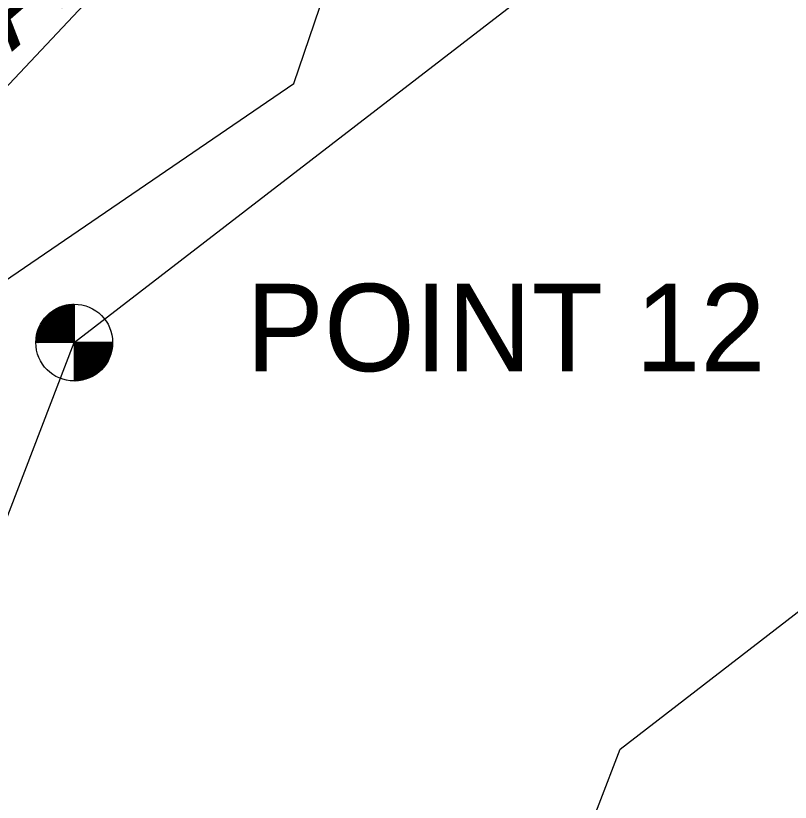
# Model space of a CAD drawing. Extents: x 2091245 to 2092168, y 863656 to 864307.
# Drawn here: x 2091740.16 to 2091775.62, y 863974.81 to 864010.83 of the extents above; entities that cross this region are included whole.
import ezdxf

# ---------------------------------------------------------------- set-up
doc = ezdxf.new("R2010")
doc.units = 0
for name, color, linetype in [('Exist Hydro Jurisdictional Stream or Body of Water', 7, 'Continuous'), ('Exist Hydrographic Top of Bank', 7, 'Continuous'), ('Prop Boundary Buffer Zone 1', 7, 'Continuous'), ('Prop Boundary Buffer Zone 2', 7, 'Continuous'), ('Scratch_Level_6', 7, 'Continuous')]:
    doc.layers.add(name, color=color, linetype=linetype)

msp = doc.modelspace()

# ---------------------------------------------------------------- linework, layer by layer
at = {"layer": 'Exist Hydro Jurisdictional Stream or Body of Water'}
msp.add_lwpolyline([(2091673.038, 863927.911), (2091672.627, 863930.924), (2091675.297, 863933.324), (2091682.95, 863933.761), (2091691.963, 863933.051), (2091695.28, 863934.846), (2091701.524, 863942.139), (2091700.79, 863950.834), (2091700.072, 863952.463), (2091701.052, 863960.667), (2091705.84, 863965.844), (2091716.038, 863968.921), (2091730.163, 863972.743), (2091727.795, 863981.975), (2091728.219, 863990.873), (2091752.896, 864007.718), (2091756.927, 864019.571), (2091767.092, 864026.792), (2091774.676, 864028.045), (2091779.207, 864034.48), (2091785.465, 864035.877), (2091790.325, 864037.563), (2091800.277, 864042.765), (2091802.985, 864045.288)], dxfattribs=at)
at = {"layer": 'Exist Hydrographic Top of Bank'}
msp.add_lwpolyline([(2091672.3, 863948.34), (2091672.795, 863927.55), (2091675.886, 863922.062), (2091703.915, 863935.563), (2091732.111, 863967.919), (2091742.84, 863995.86), (2091771.423, 864017.904), (2091796.939, 864035.122), (2091802.35, 864043.97), (2091798.347, 864050.35), (2091774.513, 864034.247), (2091751.1, 864019.64), (2091722.53, 863989.28), (2091717.91, 863987.56), (2091701.99, 863966.43)], close=True, dxfattribs=at)
at = {"layer": 'Prop Boundary Buffer Zone 1'}
msp.add_lwpolyline([(2091641.896, 863964.945), (2091642.981, 863919.351), (2091663.555, 863882.824), (2091722.485, 863911.209), (2091758.215, 863952.211), (2091767.828, 863977.246), (2091788.992, 863993.568), (2091819.128, 864013.904), (2091837.639, 864044.171), (2091807.267, 864092.583), (2091758.17, 864059.411), (2091731.919, 864043.033), (2091705.49, 864014.948), (2091699.226, 864012.616), (2091681.482, 863989.064)], close=True, dxfattribs=at)
at = {"layer": 'Prop Boundary Buffer Zone 2'}
msp.add_lwpolyline([(2091688.904, 863895.034), (2091722.485, 863911.209), (2091758.215, 863952.211), (2091767.828, 863977.246), (2091788.992, 863993.568), (2091813.72, 864010.255)], dxfattribs=at)
at = {"layer": 'Scratch_Level_6'}
for p, q in [((2091741.083, 863995.894), (2091742.806, 863997.617)), ((2091741.084, 863995.93), (2091742.77, 863997.616)), ((2091741.084, 863995.86), (2091742.84, 863997.616)), ((2091741.086, 863995.967), (2091742.733, 863997.614)), ((2091741.088, 863996.005), (2091742.694, 863997.611)), ((2091741.092, 863996.045), (2091742.656, 863997.608)), ((2091741.097, 863996.085), (2091742.615, 863997.603)), ((2091741.103, 863996.126), (2091742.574, 863997.597)), ((2091741.11, 863996.168), (2091742.532, 863997.59)), ((2091741.118, 863996.212), (2091742.488, 863997.582)), ((2091741.12, 863995.86), (2091742.84, 863997.58)), ((2091741.128, 863996.257), (2091742.443, 863997.572)), ((2091741.139, 863996.304), (2091742.396, 863997.56)), ((2091741.153, 863996.353), (2091742.347, 863997.547)), ((2091741.155, 863995.86), (2091742.84, 863997.545)), ((2091741.169, 863996.404), (2091742.296, 863997.531)), ((2091741.187, 863996.458), (2091742.242, 863997.513)), ((2091741.19, 863995.86), (2091742.84, 863997.51)), ((2091741.209, 863996.515), (2091742.185, 863997.491)), ((2091741.226, 863995.86), (2091742.84, 863997.474)), ((2091741.235, 863996.576), (2091742.123, 863997.465)), ((2091741.261, 863995.86), (2091742.84, 863997.439)), ((2091741.266, 863996.643), (2091742.057, 863997.433)), ((2091741.296, 863995.86), (2091742.84, 863997.404)), ((2091741.306, 863996.718), (2091741.982, 863997.394)), ((2091741.332, 863995.86), (2091742.84, 863997.368)), ((2091741.359, 863996.806), (2091741.894, 863997.341)), ((2091741.367, 863995.86), (2091742.84, 863997.333)), ((2091741.863, 863997.321), (2091742.84, 863996.344)), ((2091741.884, 863997.335), (2091742.84, 863996.379)), ((2091741.906, 863997.349), (2091742.84, 863996.415)), ((2091741.928, 863997.362), (2091742.84, 863996.45)), ((2091741.95, 863997.376), (2091742.84, 863996.485)), ((2091741.972, 863997.388), (2091742.84, 863996.521)), ((2091741.995, 863997.401), (2091742.84, 863996.556)), ((2091742.018, 863997.413), (2091742.84, 863996.592)), ((2091742.041, 863997.426), (2091742.84, 863996.627)), ((2091742.065, 863997.437), (2091742.84, 863996.662)), ((2091742.089, 863997.449), (2091742.84, 863996.698)), ((2091742.113, 863997.46), (2091742.84, 863996.733)), ((2091742.137, 863997.471), (2091742.84, 863996.768)), ((2091742.162, 863997.482), (2091742.84, 863996.804)), ((2091742.187, 863997.492), (2091742.84, 863996.839)), ((2091742.213, 863997.502), (2091742.84, 863996.874)), ((2091742.238, 863997.511), (2091742.84, 863996.91)), ((2091742.264, 863997.521), (2091742.84, 863996.945)), ((2091742.291, 863997.53), (2091742.84, 863996.98)), ((2091742.318, 863997.538), (2091742.84, 863997.016)), ((2091742.345, 863997.546), (2091742.84, 863997.051)), ((2091742.372, 863997.554), (2091742.84, 863997.087)), ((2091742.4, 863997.562), (2091742.84, 863997.122)), ((2091742.428, 863997.569), (2091742.84, 863997.157)), ((2091742.457, 863997.575), (2091742.84, 863997.193)), ((2091742.486, 863997.582), (2091742.84, 863997.228)), ((2091742.516, 863997.587), (2091742.84, 863997.263)), ((2091742.546, 863997.593), (2091742.84, 863997.299)), ((2091742.576, 863997.598), (2091742.84, 863997.334)), ((2091742.607, 863997.602), (2091742.84, 863997.369)), ((2091742.639, 863997.606), (2091742.84, 863997.405)), ((2091742.671, 863997.609), (2091742.84, 863997.44)), ((2091742.703, 863997.612), (2091742.84, 863997.475)), ((2091742.736, 863997.615), (2091742.84, 863997.511)), ((2091742.77, 863997.616), (2091742.84, 863997.546)), ((2091742.804, 863997.617), (2091742.84, 863997.582)), ((2091742.839, 863997.618), (2091742.84, 863997.617)), ((2091742.84, 863997.618), (2091742.84, 863994.102)), ((2091741.403, 863995.86), (2091742.84, 863997.297)), ((2091741.438, 863995.86), (2091742.84, 863997.262)), ((2091741.441, 863996.923), (2091741.777, 863997.259)), ((2091741.473, 863995.86), (2091742.84, 863997.227)), ((2091741.475, 863996.967), (2091742.582, 863995.86)), ((2091741.491, 863996.986), (2091742.617, 863995.86)), ((2091741.507, 863997.005), (2091742.652, 863995.86)), ((2091741.509, 863995.86), (2091742.84, 863997.191)), ((2091741.523, 863997.024), (2091742.688, 863995.86)), ((2091741.54, 863997.043), (2091742.723, 863995.86)), ((2091741.544, 863995.86), (2091742.84, 863997.156)), ((2091741.557, 863997.061), (2091742.758, 863995.86)), ((2091741.574, 863997.079), (2091742.794, 863995.86)), ((2091741.579, 863995.86), (2091742.84, 863997.121)), ((2091741.592, 863997.097), (2091742.829, 863995.86)), ((2091741.609, 863997.115), (2091742.84, 863995.884)), ((2091741.615, 863995.86), (2091742.84, 863997.085)), ((2091741.628, 863997.132), (2091742.84, 863995.92)), ((2091741.646, 863997.149), (2091742.84, 863995.955)), ((2091741.65, 863995.86), (2091742.84, 863997.05)), ((2091741.664, 863997.166), (2091742.84, 863995.991)), ((2091741.683, 863997.183), (2091742.84, 863996.026)), ((2091741.685, 863995.86), (2091742.84, 863997.015)), ((2091741.702, 863997.199), (2091742.84, 863996.061)), ((2091741.721, 863997.215), (2091742.84, 863996.097)), ((2091741.721, 863995.86), (2091742.84, 863996.979)), ((2091741.741, 863997.231), (2091742.84, 863996.132)), ((2091741.76, 863997.247), (2091742.84, 863996.167)), ((2091741.78, 863997.262), (2091742.84, 863996.203)), ((2091741.801, 863997.277), (2091742.84, 863996.238)), ((2091741.821, 863997.292), (2091742.84, 863996.273)), ((2091741.842, 863997.307), (2091742.84, 863996.309)), ((2091741.244, 863996.596), (2091741.981, 863995.86)), ((2091741.255, 863996.62), (2091742.016, 863995.86)), ((2091741.267, 863996.644), (2091742.051, 863995.86)), ((2091741.279, 863996.668), (2091742.087, 863995.86)), ((2091741.291, 863996.691), (2091742.122, 863995.86)), ((2091741.304, 863996.714), (2091742.157, 863995.86)), ((2091741.316, 863996.736), (2091742.193, 863995.86)), ((2091741.33, 863996.759), (2091742.228, 863995.86)), ((2091741.343, 863996.781), (2091742.263, 863995.86)), ((2091741.356, 863996.802), (2091742.299, 863995.86)), ((2091741.37, 863996.824), (2091742.334, 863995.86)), ((2091741.384, 863996.845), (2091742.369, 863995.86)), ((2091741.399, 863996.866), (2091742.405, 863995.86)), ((2091741.413, 863996.887), (2091742.44, 863995.86)), ((2091741.428, 863996.907), (2091742.476, 863995.86)), ((2091741.444, 863996.927), (2091742.511, 863995.86)), ((2091741.459, 863996.947), (2091742.546, 863995.86)), ((2091741.756, 863995.86), (2091742.84, 863996.944)), ((2091741.791, 863995.86), (2091742.84, 863996.909)), ((2091741.827, 863995.86), (2091742.84, 863996.873)), ((2091741.862, 863995.86), (2091742.84, 863996.838)), ((2091741.898, 863995.86), (2091742.84, 863996.802)), ((2091741.933, 863995.86), (2091742.84, 863996.767)), ((2091741.968, 863995.86), (2091742.84, 863996.732)), ((2091742.004, 863995.86), (2091742.84, 863996.696)), ((2091742.039, 863995.86), (2091742.84, 863996.661)), ((2091742.074, 863995.86), (2091742.84, 863996.626)), ((2091742.11, 863995.86), (2091742.84, 863996.59)), ((2091741.127, 863996.254), (2091741.521, 863995.86)), ((2091741.134, 863996.282), (2091741.556, 863995.86)), ((2091741.141, 863996.311), (2091741.592, 863995.86)), ((2091741.149, 863996.338), (2091741.627, 863995.86)), ((2091741.157, 863996.366), (2091741.662, 863995.86)), ((2091741.165, 863996.393), (2091741.698, 863995.86)), ((2091741.174, 863996.419), (2091741.733, 863995.86)), ((2091741.183, 863996.446), (2091741.768, 863995.86)), ((2091741.192, 863996.472), (2091741.804, 863995.86)), ((2091741.202, 863996.497), (2091741.839, 863995.86)), ((2091741.212, 863996.523), (2091741.874, 863995.86)), ((2091741.222, 863996.547), (2091741.91, 863995.86)), ((2091741.233, 863996.572), (2091741.945, 863995.86)), ((2091742.145, 863995.86), (2091742.84, 863996.555)), ((2091742.18, 863995.86), (2091742.84, 863996.52)), ((2091742.216, 863995.86), (2091742.84, 863996.484)), ((2091742.251, 863995.86), (2091742.84, 863996.449)), ((2091742.286, 863995.86), (2091742.84, 863996.414)), ((2091742.322, 863995.86), (2091742.84, 863996.378)), ((2091742.357, 863995.86), (2091742.84, 863996.343)), ((2091742.393, 863995.86), (2091742.84, 863996.307)), ((2091742.428, 863995.86), (2091742.84, 863996.272)), ((2091742.463, 863995.86), (2091742.84, 863996.237)), ((2091741.082, 863995.874), (2091741.097, 863995.86)), ((2091741.083, 863995.909), (2091741.132, 863995.86)), ((2091741.084, 863995.943), (2091741.167, 863995.86)), ((2091741.086, 863995.976), (2091741.203, 863995.86)), ((2091741.089, 863996.009), (2091741.238, 863995.86)), ((2091741.092, 863996.042), (2091741.273, 863995.86)), ((2091741.095, 863996.074), (2091741.309, 863995.86)), ((2091741.1, 863996.105), (2091741.344, 863995.86)), ((2091741.104, 863996.135), (2091741.38, 863995.86)), ((2091741.109, 863996.166), (2091741.415, 863995.86)), ((2091741.115, 863996.196), (2091741.45, 863995.86)), ((2091741.121, 863996.225), (2091741.486, 863995.86)), ((2091742.499, 863995.86), (2091742.84, 863996.201)), ((2091742.534, 863995.86), (2091742.84, 863996.166)), ((2091742.569, 863995.86), (2091742.84, 863996.131)), ((2091742.605, 863995.86), (2091742.84, 863996.095)), ((2091742.64, 863995.86), (2091742.84, 863996.06)), ((2091742.675, 863995.86), (2091742.84, 863996.025)), ((2091742.711, 863995.86), (2091742.84, 863995.989)), ((2091742.746, 863995.86), (2091742.84, 863995.954)), ((2091742.781, 863995.86), (2091742.84, 863995.919)), ((2091742.817, 863995.86), (2091742.84, 863995.883)), ((2091744.598, 863995.86), (2091741.082, 863995.86)), ((2091742.84, 863995.825), (2091742.875, 863995.86)), ((2091742.84, 863995.79), (2091742.91, 863995.86)), ((2091742.84, 863995.755), (2091742.945, 863995.86)), ((2091742.84, 863995.719), (2091742.981, 863995.86)), ((2091742.84, 863995.684), (2091743.016, 863995.86)), ((2091742.84, 863995.649), (2091743.051, 863995.86)), ((2091742.84, 863995.613), (2091743.087, 863995.86)), ((2091742.84, 863995.578), (2091743.122, 863995.86)), ((2091742.84, 863995.543), (2091743.157, 863995.86)), ((2091742.84, 863995.507), (2091743.193, 863995.86)), ((2091742.84, 863995.472), (2091743.228, 863995.86)), ((2091742.84, 863995.437), (2091743.263, 863995.86)), ((2091742.84, 863995.401), (2091743.299, 863995.86)), ((2091742.84, 863995.366), (2091743.334, 863995.86)), ((2091742.84, 863995.331), (2091743.369, 863995.86)), ((2091742.84, 863995.295), (2091743.405, 863995.86)), ((2091742.84, 863995.26), (2091743.44, 863995.86)), ((2091742.84, 863995.224), (2091743.476, 863995.86)), ((2091742.84, 863995.189), (2091743.511, 863995.86)), ((2091742.84, 863995.154), (2091743.546, 863995.86)), ((2091742.84, 863995.118), (2091743.582, 863995.86)), ((2091742.84, 863995.083), (2091743.617, 863995.86)), ((2091742.84, 863995.048), (2091743.652, 863995.86)), ((2091742.84, 863995.012), (2091743.688, 863995.86)), ((2091742.84, 863994.977), (2091743.723, 863995.86)), ((2091742.84, 863994.942), (2091743.758, 863995.86)), ((2091742.84, 863994.906), (2091743.794, 863995.86)), ((2091742.84, 863994.871), (2091743.829, 863995.86)), ((2091742.84, 863994.836), (2091743.864, 863995.86)), ((2091742.84, 863994.8), (2091743.9, 863995.86)), ((2091742.84, 863994.765), (2091743.935, 863995.86)), ((2091742.84, 863994.729), (2091743.971, 863995.86)), ((2091742.84, 863994.694), (2091744.006, 863995.86)), ((2091742.84, 863994.659), (2091744.041, 863995.86)), ((2091742.84, 863994.623), (2091744.077, 863995.86)), ((2091742.84, 863994.588), (2091744.112, 863995.86)), ((2091742.84, 863994.553), (2091744.147, 863995.86)), ((2091742.84, 863994.517), (2091744.183, 863995.86)), ((2091742.84, 863994.482), (2091744.218, 863995.86)), ((2091742.84, 863994.447), (2091744.253, 863995.86)), ((2091742.84, 863994.411), (2091744.289, 863995.86)), ((2091742.84, 863994.376), (2091744.324, 863995.86)), ((2091742.84, 863994.341), (2091744.359, 863995.86)), ((2091742.84, 863994.305), (2091744.395, 863995.86)), ((2091742.84, 863994.27), (2091744.43, 863995.86)), ((2091742.84, 863994.234), (2091744.466, 863995.86)), ((2091742.84, 863994.199), (2091744.501, 863995.86)), ((2091742.84, 863994.164), (2091744.536, 863995.86)), ((2091742.84, 863994.128), (2091744.572, 863995.86)), ((2091742.84, 863995.855), (2091744.08, 863994.615)), ((2091742.84, 863995.82), (2091744.062, 863994.597)), ((2091742.84, 863995.784), (2091744.044, 863994.58)), ((2091742.84, 863995.749), (2091744.026, 863994.563)), ((2091742.84, 863995.714), (2091744.007, 863994.546)), ((2091742.84, 863995.678), (2091743.989, 863994.53)), ((2091742.84, 863995.643), (2091743.969, 863994.513)), ((2091742.84, 863995.607), (2091743.95, 863994.497)), ((2091742.84, 863995.572), (2091743.931, 863994.482)), ((2091742.84, 863995.537), (2091743.911, 863994.466)), ((2091742.849, 863994.102), (2091744.598, 863995.851)), ((2091742.87, 863995.86), (2091744.098, 863994.632)), ((2091742.885, 863994.103), (2091744.597, 863995.815)), ((2091742.906, 863995.86), (2091744.115, 863994.65)), ((2091742.922, 863994.104), (2091744.596, 863995.778)), ((2091742.941, 863995.86), (2091744.132, 863994.669)), ((2091742.959, 863994.106), (2091744.593, 863995.74)), ((2091742.976, 863995.86), (2091744.149, 863994.687)), ((2091742.998, 863994.11), (2091744.591, 863995.702)), ((2091743.012, 863995.86), (2091744.166, 863994.706)), ((2091743.037, 863994.114), (2091744.586, 863995.663)), ((2091743.047, 863995.86), (2091744.182, 863994.725)), ((2091743.077, 863994.118), (2091744.581, 863995.622)), ((2091743.082, 863995.86), (2091744.198, 863994.744)), ((2091743.118, 863995.86), (2091744.214, 863994.764)), ((2091743.119, 863994.125), (2091744.575, 863995.581)), ((2091743.153, 863995.86), (2091744.23, 863994.784)), ((2091743.162, 863994.132), (2091744.568, 863995.538)), ((2091743.189, 863995.86), (2091744.245, 863994.804)), ((2091743.224, 863995.86), (2091744.26, 863994.824)), ((2091743.259, 863995.86), (2091744.275, 863994.845)), ((2091743.295, 863995.86), (2091744.289, 863994.865)), ((2091743.33, 863995.86), (2091744.303, 863994.887)), ((2091743.365, 863995.86), (2091744.317, 863994.908)), ((2091743.401, 863995.86), (2091744.331, 863994.929)), ((2091743.436, 863995.86), (2091744.344, 863994.952)), ((2091743.471, 863995.86), (2091744.358, 863994.974)), ((2091743.507, 863995.86), (2091744.371, 863994.996)), ((2091743.542, 863995.86), (2091744.383, 863995.019)), ((2091743.577, 863995.86), (2091744.396, 863995.042)), ((2091743.613, 863995.86), (2091744.408, 863995.065)), ((2091743.648, 863995.86), (2091744.419, 863995.089)), ((2091743.683, 863995.86), (2091744.431, 863995.113)), ((2091743.719, 863995.86), (2091744.442, 863995.137)), ((2091743.754, 863995.86), (2091744.453, 863995.161)), ((2091743.79, 863995.86), (2091744.463, 863995.186)), ((2091743.825, 863995.86), (2091744.473, 863995.211)), ((2091743.86, 863995.86), (2091744.483, 863995.237)), ((2091743.896, 863995.86), (2091744.493, 863995.263)), ((2091743.931, 863995.86), (2091744.502, 863995.289)), ((2091743.966, 863995.86), (2091744.511, 863995.315)), ((2091744.002, 863995.86), (2091744.52, 863995.342)), ((2091744.037, 863995.86), (2091744.528, 863995.369)), ((2091744.072, 863995.86), (2091744.535, 863995.397)), ((2091744.108, 863995.86), (2091744.543, 863995.425)), ((2091744.143, 863995.86), (2091744.55, 863995.453)), ((2091744.178, 863995.86), (2091744.556, 863995.482)), ((2091744.214, 863995.86), (2091744.563, 863995.511)), ((2091744.249, 863995.86), (2091744.568, 863995.541)), ((2091744.285, 863995.86), (2091744.574, 863995.571)), ((2091744.32, 863995.86), (2091744.578, 863995.601)), ((2091744.355, 863995.86), (2091744.583, 863995.632)), ((2091744.391, 863995.86), (2091744.587, 863995.664)), ((2091744.426, 863995.86), (2091744.59, 863995.696)), ((2091744.461, 863995.86), (2091744.593, 863995.729)), ((2091744.497, 863995.86), (2091744.595, 863995.762)), ((2091744.532, 863995.86), (2091744.596, 863995.796)), ((2091744.567, 863995.86), (2091744.597, 863995.83)), ((2091742.84, 863995.501), (2091743.891, 863994.451)), ((2091742.84, 863995.466), (2091743.87, 863994.436)), ((2091742.84, 863995.431), (2091743.849, 863994.421)), ((2091742.84, 863995.395), (2091743.829, 863994.407)), ((2091742.84, 863995.36), (2091743.807, 863994.393)), ((2091742.84, 863995.325), (2091743.786, 863994.379)), ((2091742.84, 863995.289), (2091743.764, 863994.365)), ((2091742.84, 863995.254), (2091743.742, 863994.352)), ((2091742.84, 863995.219), (2091743.72, 863994.339)), ((2091742.84, 863995.183), (2091743.697, 863994.326)), ((2091743.206, 863994.141), (2091744.559, 863995.494)), ((2091743.252, 863994.151), (2091744.549, 863995.448)), ((2091743.299, 863994.163), (2091744.536, 863995.401)), ((2091743.349, 863994.178), (2091744.522, 863995.351)), ((2091743.401, 863994.194), (2091744.506, 863995.299)), ((2091743.456, 863994.214), (2091744.486, 863995.245)), ((2091743.514, 863994.237), (2091744.463, 863995.186)), ((2091742.84, 863995.148), (2091743.675, 863994.313)), ((2091742.84, 863995.112), (2091743.652, 863994.301)), ((2091742.84, 863995.077), (2091743.628, 863994.289)), ((2091742.84, 863995.042), (2091743.604, 863994.277)), ((2091742.84, 863995.006), (2091743.58, 863994.266)), ((2091742.84, 863994.971), (2091743.556, 863994.255)), ((2091742.84, 863994.936), (2091743.532, 863994.244)), ((2091742.84, 863994.9), (2091743.507, 863994.234)), ((2091742.84, 863994.865), (2091743.481, 863994.224)), ((2091742.84, 863994.83), (2091743.456, 863994.214)), ((2091742.84, 863994.794), (2091743.43, 863994.204)), ((2091743.577, 863994.264), (2091744.436, 863995.123)), ((2091743.646, 863994.298), (2091744.402, 863995.054)), ((2091743.725, 863994.341), (2091744.359, 863994.976)), ((2091743.819, 863994.401), (2091744.3, 863994.881)), ((2091742.84, 863994.759), (2091743.404, 863994.195)), ((2091742.84, 863994.724), (2091743.377, 863994.186)), ((2091742.84, 863994.688), (2091743.35, 863994.178)), ((2091742.84, 863994.653), (2091743.323, 863994.17)), ((2091742.84, 863994.618), (2091743.295, 863994.162)), ((2091742.84, 863994.582), (2091743.267, 863994.155)), ((2091742.84, 863994.547), (2091743.239, 863994.148)), ((2091742.84, 863994.511), (2091743.21, 863994.142)), ((2091742.84, 863994.476), (2091743.18, 863994.136)), ((2091742.84, 863994.441), (2091743.151, 863994.13)), ((2091743.958, 863994.504), (2091744.197, 863994.743)), ((2091742.84, 863994.405), (2091743.12, 863994.125)), ((2091742.84, 863994.37), (2091743.09, 863994.12)), ((2091742.84, 863994.335), (2091743.059, 863994.116)), ((2091742.84, 863994.299), (2091743.027, 863994.112)), ((2091742.84, 863994.264), (2091742.995, 863994.109)), ((2091742.84, 863994.229), (2091742.962, 863994.107)), ((2091742.84, 863994.193), (2091742.929, 863994.105)), ((2091742.84, 863994.158), (2091742.895, 863994.103)), ((2091742.84, 863994.123), (2091742.86, 863994.103))]:
    msp.add_line(p, q, dxfattribs=at)
msp.add_circle((2091742.84, 863995.86), 1.758, dxfattribs=at)

# ---------------------------------------------------------------- texts
msp.add_text('TOP OF BANK', height=4, rotation=41.0345, dxfattribs=at).set_placement((2091721.149, 863992.775))
msp.add_text('POINT 12', height=4, dxfattribs=at).set_placement((2091750.706, 863994.551))

doc.saveas('drawing.dxf')
